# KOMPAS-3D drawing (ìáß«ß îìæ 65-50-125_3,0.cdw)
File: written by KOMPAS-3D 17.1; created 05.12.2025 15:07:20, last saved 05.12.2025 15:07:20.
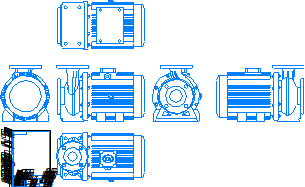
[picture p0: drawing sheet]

Sheet 1: A4, portrait

Title block, sheet 1: name: Насос МНС / 65-50-125_3,0; material: Сталь 10  ГОСТ 1050-88; mass: 118,55; sheets: 1; sheet format: A4

Views: Проекционный вид 2, Проекционный вид 3, Проекционный вид 4, Проекционный вид 5, Проекционный вид 6
Referenced files in \\adlc.lan\data\АДЛ_ПКД\3D-модели\ADL production\Насосы ГРАНПАМП\Насосы ГРАНПАМП серии МНС\KOMPAS 3D\: Насос МНС 65-50-125_3,0.m3d
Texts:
  Andrey
  АДЛ
Dimensions and other numbers on the sheet: 1:1; 1; 65-50-125_3,0; 118,55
